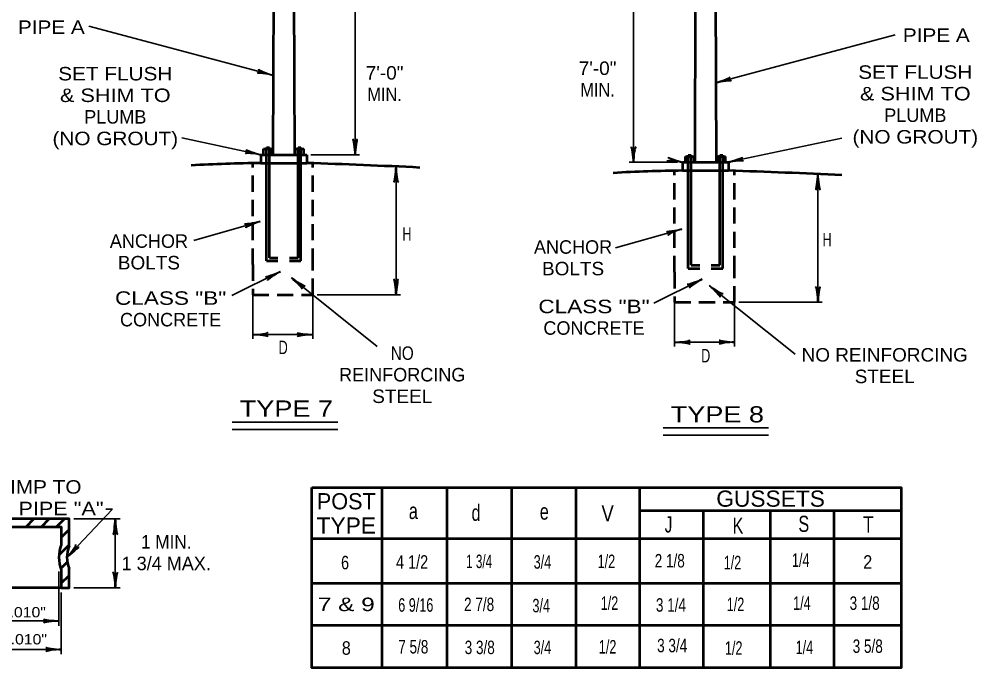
# Model space of a CAD drawing. Extents: x -209 to 471, y -242 to 199.
# Drawn here: x -54 to 123.5, y -36.8 to 83.5 of the extents above; entities that cross this region are included whole.
import ezdxf
from ezdxf.enums import TextEntityAlignment as Align

# ---------------------------------------------------------------- set-up
doc = ezdxf.new("R2010")
doc.units = 0
doc.linetypes.add('MEDIUM_DASHED', pattern=[4.5, 3, -1.5])
doc.layers.add('1', color=7, linetype='Continuous', lineweight=53)

msp = doc.modelspace()

# ---------------------------------------------------------------- linework, layer by layer
at = {"layer": '1'}
for p, q in [((71.432, 137.136), (71.21, 56.943)), ((74.868, 137.136), (75.201, 56.943)), ((-6.783, 119.865), (-6.954, 58.346)), ((-3.218, 119.865), (-2.963, 58.346)), ((-8.684, 58.346), (-8.684, 59.411)), ((-8.684, 59.411), (-7.087, 59.411)), ((-8.232, 59.411), (-8.232, 59.49)), ((-8.232, 59.49), (-7.54, 59.49)), ((-8.152, 59.677), (-7.62, 59.677)), ((-8.152, 59.49), (-8.152, 59.677)), ((-8.152, 38.651), (-8.152, 59.411)), ((-7.62, 59.49), (-7.62, 59.677)), ((-7.62, 39.257), (-7.62, 59.411)), ((-7.54, 59.411), (-7.54, 59.49)), ((-7.087, 58.346), (-7.087, 59.411)), ((-2.83, 59.411), (-1.233, 59.411)), ((-2.83, 58.346), (-2.83, 59.411)), ((-2.378, 59.411), (-2.378, 59.49)), ((-2.378, 59.49), (-1.686, 59.49)), ((-2.298, 59.677), (-1.765, 59.677)), ((-2.298, 59.49), (-2.298, 59.677)), ((-2.298, 39.257), (-2.298, 59.411)), ((-1.765, 59.49), (-1.765, 59.677)), ((-1.765, 38.651), (-1.765, 59.411)), ((-1.686, 59.411), (-1.686, 59.49)), ((-1.233, 58.346), (-1.233, 59.411)), ((-9.217, 58.346), (-0.701, 58.346)), ((-9.217, 58.346), (-9.217, 56.795)), ((-9.217, 56.795), (-0.701, 56.795)), ((-0.701, 58.346), (-0.701, 56.795)), ((68.947, 56.943), (77.464, 56.943)), ((68.947, 56.943), (68.947, 55.393)), ((69.48, 56.943), (69.48, 58.008)), ((69.48, 58.008), (71.077, 58.008)), ((69.932, 58.008), (69.932, 58.088)), ((69.932, 58.088), (70.624, 58.088)), ((70.012, 58.274), (70.545, 58.274)), ((70.012, 58.088), (70.012, 58.274)), ((70.012, 37.249), (70.012, 58.008)), ((70.545, 58.088), (70.545, 58.274)), ((70.545, 37.855), (70.545, 58.008)), ((70.624, 58.008), (70.624, 58.088)), ((71.077, 56.943), (71.077, 58.008)), ((75.334, 58.008), (76.931, 58.008)), ((75.334, 56.943), (75.334, 58.008)), ((75.787, 58.008), (75.787, 58.088)), ((75.787, 58.088), (76.479, 58.088)), ((75.866, 58.274), (76.399, 58.274)), ((75.866, 58.088), (75.866, 58.274)), ((75.866, 37.855), (75.866, 58.008)), ((76.399, 58.088), (76.399, 58.274)), ((76.399, 37.249), (76.399, 58.008)), ((76.479, 58.008), (76.479, 58.088)), ((76.931, 56.943), (76.931, 58.008)), ((77.464, 56.943), (77.464, 55.393)), ((68.947, 55.393), (77.464, 55.393)), ((-7.62, 39.257), (-6.022, 39.257)), ((-3.893, 39.257), (-2.298, 39.257)), ((-8.152, 38.651), (-6.022, 38.651)), ((-3.893, 38.651), (-1.765, 38.651)), ((70.545, 37.855), (72.142, 37.855)), ((74.271, 37.855), (75.866, 37.855)), ((70.012, 37.249), (72.142, 37.249)), ((74.271, 37.249), (76.399, 37.249)), ((13.258, -36.8), (13.258, -3.345)), ((25.299, -36.8), (25.299, -3.345)), ((37.341, -36.8), (37.341, -3.345)), ((49.261, -36.8), (49.261, -3.345)), ((61.059, -36.8), (61.059, -3.345)), ((61.059, -7.602), (109.469, -7.602)), ((72.858, -36.8), (72.858, -7.602)), ((85.264, -36.8), (85.264, -7.602)), ((97.062, -36.8), (97.062, -7.602)), ((-52.695, -10.659), (-51.231, -9.195)), ((-49.866, -10.659), (-48.402, -9.195)), ((-47.038, -10.659), (-45.574, -9.195)), ((-46.185, -12.634), (-44.721, -11.17)), ((-46.572, -15.851), (-44.721, -13.999)), ((0.242, -12.833), (109.469, -12.833)), ((-46.27, -18.376), (-45.048, -17.155)), ((-46.185, -21.12), (-44.721, -19.656)), ((0.242, -21.107), (109.469, -21.107)), ((-46.185, -21.957), (-80.281, -21.957)), ((0.242, -28.893), (109.469, -28.893))]:
    msp.add_line(p, q, dxfattribs=at)
at = {"layer": '1', "lineweight": 35}
for p, q in [((8.275, 88.009), (8.275, 58.346)), ((59.861, 86.607), (59.861, 56.943)), ((-6.979, 73.071), (-41.042, 82.196)), ((75.114, 71.669), (108.351, 80.572)), ((-9.217, 58.346), (-23.865, 61.453)), ((77.353, 56.943), (98.46, 61.421)), ((0.098, 58.346), (9.073, 58.346)), ((68.038, 56.943), (59.063, 56.943)), ((15.864, 32.382), (15.864, 56.123)), ((94.028, 30.98), (94.028, 54.721)), ((-9.35, 45.968), (-21.64, 42.469)), ((68.814, 44.565), (56.525, 41.067)), ((-5.594, 36.664), (-14.556, 32.225)), ((-3.5, 35.522), (12.375, 22.802)), ((72.57, 35.261), (63.608, 30.822)), ((73.934, 34.066), (89.809, 21.346)), ((-10.685, 32.382), (-10.685, 24.19)), ((0.428, 32.382), (0.428, 24.19)), ((1.227, 32.382), (16.662, 32.382)), ((67.479, 30.98), (67.479, 22.788)), ((78.593, 30.98), (78.593, 22.788)), ((79.391, 30.98), (94.827, 30.98)), ((-10.685, 24.989), (0.428, 24.989)), ((67.479, 23.586), (78.593, 23.586)), ((-14.516, 8.784), (5.045, 8.784)), ((-14.516, 7.418), (5.045, 7.418)), ((65.341, 7.715), (84.902, 7.715)), ((65.341, 6.35), (84.902, 6.35)), ((-45.135, -16.308), (-36.81, -7.517)), ((-37.91, -7.366), (-36.667, -7.366)), ((-43.842, -9.195), (-35.292, -9.195)), ((-36.17, -9.195), (-36.17, -21.957)), ((-46.599, -18.944), (-46.599, -28.988)), ((-46.185, -22.836), (-46.185, -34.273)), ((-43.842, -21.957), (-35.292, -21.957)), ((-79.864, -28.109), (-46.599, -28.109)), ((-80.281, -33.395), (-46.185, -33.395))]:
    msp.add_line(p, q, dxfattribs=at)
at = {"layer": '1', "linetype": 'MEDIUM_DASHED'}
for p, q in [((-10.685, 37.975), (-10.685, 56.78)), ((0.428, 37.975), (0.428, 56.76)), ((67.479, 36.572), (67.479, 55.377)), ((78.593, 36.572), (78.593, 55.357))]:
    msp.add_line(p, q, dxfattribs=at)
for points in [[(-10.685, 37.975), (-10.685, 32.382), (0.428, 32.382), (0.428, 37.975)], [(-10.685, 37.975), (-10.685, 32.382), (0.428, 32.382), (0.428, 37.975)], [(67.479, 36.572), (67.479, 30.98), (78.593, 30.98), (78.593, 36.572)], [(67.479, 36.572), (67.479, 30.98), (78.593, 30.98), (78.593, 36.572)]]:
    msp.add_lwpolyline(points, dxfattribs=at)
at = {"layer": '1'}
msp.add_lwpolyline([(0.242, -3.345), (109.469, -3.345), (109.469, -36.8), (0.242, -36.8)], close=True, dxfattribs=at)
for points in [[(-44.721, -14.248), (-44.721, -9.195), (-81.745, -9.195)], [(-80.281, -13.966), (-80.281, -10.659), (-46.185, -10.659), (-46.185, -13.973)], [(-46.185, -18.644), (-46.185, -21.957), (-44.721, -21.957), (-44.721, -18.369)]]:
    msp.add_lwpolyline(points, dxfattribs=at)
for centre, radius, start, end in [((-7.166, -190.214), 247.017, 90.47573, 93.46734), ((-33.251, -1008.714), 1066.006, 87.12083, 88.25023), ((70.998, -191.616), 247.017, 90.47573, 93.46734), ((44.914, -1010.116), 1066.006, 87.12083, 88.25023), ((-39.797, -16.308), 6.801, 159.91344, 200.08656), ((-39.797, -16.308), 5.337, 157.29061, 202.70939)]:
    msp.add_arc(centre, radius, start, end, dxfattribs=at)
at = {"layer": '1', "lineweight": 40}
for centre, major_axis, ratio, start_param, end_param in [((-8.104, 73.087), (1.765, -0.311), 0.122415, 0.8963533, 3.1415927), ((-8.006, 73.565), (1.651, -0.624), 0.07063, 3.1407148, 5.41811), ((76.142, 72.163), (-1.651, -0.624), 0.07063, 0.8650754, 3.1424706), ((76.142, 72.163), (-1.651, -0.624), 0.07063, 0.8650754, 3.1424706), ((76.24, 71.684), (-1.765, -0.311), 0.122415, 3.1415927, 5.386832), ((76.24, 71.684), (-1.765, -0.311), 0.122415, 3.1415927, 5.386832), ((7.998, 59.437), (0.156, -1.786), 0.122415, 0.8963533, 3.1415927), ((8.486, 59.466), (-0.176, -1.756), 0.07063, 3.1407148, 5.41811), ((-10.342, 58.302), (1.779, -0.218), 0.122415, 0.8963533, 3.1415927), ((-10.269, 58.785), (1.682, -0.536), 0.07063, 3.1407148, 5.41811), ((59.65, 58.064), (0.176, -1.756), 0.07063, 0.8650754, 3.1424706), ((59.65, 58.064), (0.176, -1.756), 0.07063, 0.8650754, 3.1424706), ((60.137, 58.035), (-0.156, -1.786), 0.122415, 3.1415927, 5.386832), ((60.137, 58.035), (-0.156, -1.786), 0.122415, 3.1415927, 5.386832), ((67.823, 56.9), (1.779, -0.218), 0.122415, 0.8963533, 3.1415927), ((67.895, 57.383), (1.682, -0.536), 0.07063, 3.1407148, 5.41811), ((78.405, 57.383), (-1.682, -0.536), 0.07063, 0.8650754, 3.1424706), ((78.478, 56.9), (-1.779, -0.218), 0.122415, 3.1415927, 5.386832), ((15.652, 55.002), (0.176, 1.756), 0.07063, 3.1407148, 5.41811), ((16.14, 55.032), (-0.156, 1.786), 0.122415, 0.8963533, 3.1415927), ((93.816, 53.6), (0.176, 1.756), 0.07063, 3.1407148, 5.41811), ((93.816, 53.6), (0.176, 1.756), 0.07063, 3.1407148, 5.41811), ((94.304, 53.629), (-0.156, 1.786), 0.122415, 0.8963533, 3.1415927), ((94.304, 53.629), (-0.156, 1.786), 0.122415, 0.8963533, 3.1415927), ((-10.486, 45.864), (1.737, 0.312), 0.07063, 3.1407148, 5.41811), ((-10.486, 45.864), (1.737, 0.312), 0.07063, 3.1407148, 5.41811), ((-10.324, 45.403), (1.675, 0.639), 0.122415, 0.8963533, 3.1415927), ((-10.324, 45.403), (1.675, 0.639), 0.122415, 0.8963533, 3.1415927), ((67.679, 44.462), (1.737, 0.312), 0.07063, 3.1407148, 5.41811), ((67.679, 44.462), (1.737, 0.312), 0.07063, 3.1407148, 5.41811), ((67.84, 44.001), (1.675, 0.639), 0.122415, 0.8963533, 3.1415927), ((67.84, 44.001), (1.675, 0.639), 0.122415, 0.8963533, 3.1415927), ((-6.692, 36.356), (1.652, 0.622), 0.07063, 3.1407148, 5.41811), ((-6.692, 36.356), (1.652, 0.622), 0.07063, 3.1407148, 5.41811), ((-6.45, 35.932), (1.531, 0.932), 0.122415, 0.8963533, 3.1415927), ((-6.45, 35.932), (1.531, 0.932), 0.122415, 0.8963533, 3.1415927), ((-2.757, 34.656), (-1.261, 1.235), 0.07063, 3.1407148, 5.41811), ((-2.757, 34.656), (-1.261, 1.235), 0.07063, 3.1407148, 5.41811), ((-2.475, 35.055), (-1.491, 0.995), 0.122415, 0.8963533, 3.1415927), ((-2.475, 35.055), (-1.491, 0.995), 0.122415, 0.8963533, 3.1415927), ((15.587, 33.474), (0.156, -1.786), 0.122415, 0.8963533, 3.1415927), ((16.075, 33.503), (-0.176, -1.756), 0.07063, 3.1407148, 5.41811), ((71.472, 34.954), (1.652, 0.622), 0.07063, 3.1407148, 5.41811), ((71.472, 34.954), (1.652, 0.622), 0.07063, 3.1407148, 5.41811), ((71.715, 34.529), (1.531, 0.932), 0.122415, 0.8963533, 3.1415927), ((71.715, 34.529), (1.531, 0.932), 0.122415, 0.8963533, 3.1415927), ((74.676, 33.2), (-1.261, 1.235), 0.07063, 3.1407148, 5.41811), ((74.676, 33.2), (-1.261, 1.235), 0.07063, 3.1407148, 5.41811), ((74.959, 33.599), (-1.491, 0.995), 0.122415, 0.8963533, 3.1415927), ((74.959, 33.599), (-1.491, 0.995), 0.122415, 0.8963533, 3.1415927), ((93.752, 32.071), (0.156, -1.786), 0.122415, 0.8963533, 3.1415927), ((94.24, 32.1), (-0.176, -1.756), 0.07063, 3.1407148, 5.41811), ((-9.565, 24.777), (-1.756, 0.176), 0.07063, 3.1407148, 5.41811), ((-9.565, 24.777), (-1.756, 0.176), 0.07063, 3.1407148, 5.41811), ((-9.594, 25.265), (-1.786, -0.156), 0.122415, 0.8963533, 3.1415927), ((-9.594, 25.265), (-1.786, -0.156), 0.122415, 0.8963533, 3.1415927), ((-0.663, 24.712), (1.786, 0.156), 0.122415, 0.8963533, 3.1415927), ((-0.692, 25.2), (1.756, -0.176), 0.07063, 3.1407148, 5.41811), ((68.599, 23.375), (-1.756, 0.176), 0.07063, 3.1407148, 5.41811), ((68.599, 23.375), (-1.756, 0.176), 0.07063, 3.1407148, 5.41811), ((68.57, 23.862), (-1.786, -0.156), 0.122415, 0.8963533, 3.1415927), ((68.57, 23.862), (-1.786, -0.156), 0.122415, 0.8963533, 3.1415927), ((77.502, 23.31), (1.786, 0.156), 0.122415, 0.8963533, 3.1415927), ((77.502, 23.31), (1.786, 0.156), 0.122415, 0.8963533, 3.1415927), ((77.472, 23.798), (1.756, -0.176), 0.07063, 3.1407148, 5.41811), ((77.472, 23.798), (1.756, -0.176), 0.07063, 3.1407148, 5.41811), ((-36.382, -10.316), (0.176, 1.756), 0.07063, 3.1407148, 5.41811), ((-36.382, -10.316), (0.176, 1.756), 0.07063, 3.1407148, 5.41811), ((-35.894, -10.287), (-0.156, 1.786), 0.122415, 0.8963533, 3.1415927), ((-35.894, -10.287), (-0.156, 1.786), 0.122415, 0.8963533, 3.1415927), ((-44.586, -15.326), (-1.114, -1.404), 0.122415, 0.8963533, 3.1415927), ((-44.586, -15.326), (-1.114, -1.404), 0.122415, 0.8963533, 3.1415927), ((-44.211, -15.64), (-1.335, -1.155), 0.07063, 3.1407148, 5.41811), ((-44.211, -15.64), (-1.335, -1.155), 0.07063, 3.1407148, 5.41811), ((-36.446, -20.866), (0.156, -1.786), 0.122415, 0.8963533, 3.1415927), ((-36.446, -20.866), (0.156, -1.786), 0.122415, 0.8963533, 3.1415927), ((-35.959, -20.837), (-0.176, -1.756), 0.07063, 3.1407148, 5.41811), ((-35.959, -20.837), (-0.176, -1.756), 0.07063, 3.1407148, 5.41811), ((-47.691, -28.385), (1.786, 0.156), 0.122415, 0.8963533, 3.1415927), ((-47.691, -28.385), (1.786, 0.156), 0.122415, 0.8963533, 3.1415927), ((-47.72, -27.898), (1.756, -0.176), 0.07063, 3.1407148, 5.41811), ((-47.72, -27.898), (1.756, -0.176), 0.07063, 3.1407148, 5.41811), ((-47.276, -33.671), (1.786, 0.156), 0.122415, 0.8963533, 3.1415927), ((-47.305, -33.183), (1.756, -0.176), 0.07063, 3.1407148, 5.41811)]:
    msp.add_ellipse(centre, major_axis=major_axis, ratio=ratio, start_param=start_param, end_param=end_param, dxfattribs=at)

# ---------------------------------------------------------------- texts
at = {"layer": '1'}
for s, height, width, p in [('PIPE A', 2.5, 1.15, (-48.02, 80.754)), ('PIPE A', 2.5, 1.15, (115.964, 79.268)), ('SET FLUSH', 2.5, 1.15, (-36.164, 72.119)), ('7\'-0"', 2.5, 1.05, (13.735, 72.283)), ('7\'-0"', 2.5, 1.05, (53.201, 73.136)), ('SET FLUSH', 2.5, 1.15, (112.078, 72.421)), ('MIN.', 2.5, 0.9, (53.201, 69.136)), ('& SHIM TO', 2.5, 1.2, (-36.164, 68.119)), ('MIN.', 2.5, 0.9, (13.735, 68.283)), ('& SHIM TO', 2.5, 1.2, (112.078, 68.421)), ('(NO GROUT)', 2.5, 1.15, (-36.164, 60.119)), ('(NO GROUT)', 2.5, 1.15, (112.078, 60.421)), ('H', 2.5, 0.7, (17.866, 42.414)), ('H', 2.5, 0.7, (95.725, 41.362)), ('BOLTS', 2.5, 1.05, (-29.935, 37.082)), ('BOLTS', 2.5, 1.05, (48.657, 35.987)), ('CLASS "B"', 2.5, 1.25, (-25.908, 30.517)), ('CLASS "B"', 2.5, 1.25, (52.537, 28.965)), ('D', 2.5, 0.7, (-5.057, 21.368)), ('NO', 2.5, 0.85, (17.003, 20.308)), ('D', 2.5, 0.7, (73.237, 19.839)), ('NO REINFORCING', 2.5, 1.05, (106.408, 19.994)), ('STEEL', 2.5, 1.05, (106.408, 15.994)), ('STEEL', 2.5, 1.05, (17.003, 12.308)), ('ROLLED CRIMP TO', 2.5, 1.15, (-60.049, -4.497)), ('GUSSETS', 3, 1.05, (85.258, -6.922)), ('ENGAGE TOP PIPE "A"', 2.5, 1.2, (-60.049, -8.497)), ('a', 3, 0.75, (19.059, -9.202)), ('d', 3, 0.75, (30.68, -9.543)), ('e', 3, 0.75, (43.328, -9.316)), ('V', 3, 0.85, (55.064, -9.657)), ('J', 3, 0.7, (66.344, -11.709)), ('S', 3, 0.75, (91.41, -11.595)), ('T', 3, 0.8, (103.374, -11.709)), ('TYPE', 3, 1.05, (6.639, -11.907)), ('K', 3, 0.75, (79.219, -11.937)), ('1 MIN.', 2.5, 0.95, (-26.723, -14.687)), ('4 1/2', 2.5, 0.8, (18.831, -18.412)), ('1 3/4', 2.5, 0.65, (31.25, -18.298)), ('3/4', 2.5, 0.7, (42.986, -18.412)), ('1/2', 2.5, 0.7, (54.836, -18.298)), ('2 1/8', 2.5, 0.75, (66.571, -18.184)), ('1/2', 2.5, 0.7, (78.193, -18.526)), ('1/4', 2.5, 0.7, (90.841, -18.07)), ('2', 2.5, 0.9, (103.26, -18.412)), ('6', 2.5, 0.8, (6.411, -18.526)), ('7 & 9', 2.5, 1.35, (6.639, -26.276)), ('6 9/16', 2.5, 0.7, (19.514, -26.39)), ('2 7/8', 2.5, 0.75, (31.25, -26.276)), ('3/4', 2.5, 0.7, (42.758, -26.504)), ('1/2', 2.5, 0.7, (55.405, -26.048)), ('3 1/4', 2.5, 0.75, (66.799, -26.39)), ('1/2', 2.5, 0.7, (78.763, -26.276)), ('1/4', 2.5, 0.7, (91.068, -26.048)), ('3 1/8', 2.5, 0.75, (102.69, -26.048)), ('PIPE O.D. .025" .010"', 1.9, 1.15, (-63.303, -27.43)), ('PIPE O.D. .025" .010"', 1.9, 1.15, (-63.102, -32.45)), ('8', 2.5, 0.9, (6.639, -34.368)), ('7 5/8', 2.5, 0.75, (19.059, -34.14)), ('3 3/8', 2.5, 0.75, (31.364, -34.254)), ('3/4', 2.5, 0.7, (42.986, -34.254)), ('1/2', 2.5, 0.7, (55.064, -34.14)), ('3 3/4', 2.5, 0.75, (67.027, -33.912)), ('1/2', 2.5, 0.7, (78.421, -34.368)), ('1/4', 2.5, 0.7, (91.524, -34.254)), ('3 5/8', 2.5, 0.75, (103.26, -34.026))]:
    msp.add_text(s, height=height, dxfattribs=dict(at, width=width)).set_placement(p, align=Align.CENTER)
for s, height, p in [('PLUMB', 2.5, (-36.164, 64.119)), ('PLUMB', 2.5, (112.078, 64.421)), ('ANCHOR', 2.5, (-29.934, 41.082)), ('ANCHOR', 2.5, (48.658, 39.987)), ('CONCRETE', 2.5, (-25.908, 26.517)), ('CONCRETE', 2.5, (52.537, 24.965)), ('REINFORCING', 2.5, (17.003, 16.308)), ('POST', 3, (6.639, -7.407)), ('1 3/4 MAX.', 2.5, (-26.723, -18.687))]:
    msp.add_text(s, height=height, dxfattribs=at).set_placement(p, align=Align.CENTER)
at = {"layer": '1', "width": 1.25}
for s, p in [('TYPE 7', (-13.102, 9.78)), ('TYPE 8', (66.756, 8.711))]:
    msp.add_text(s, height=3, dxfattribs=at).set_placement(p)

doc.saveas('drawing.dxf')
